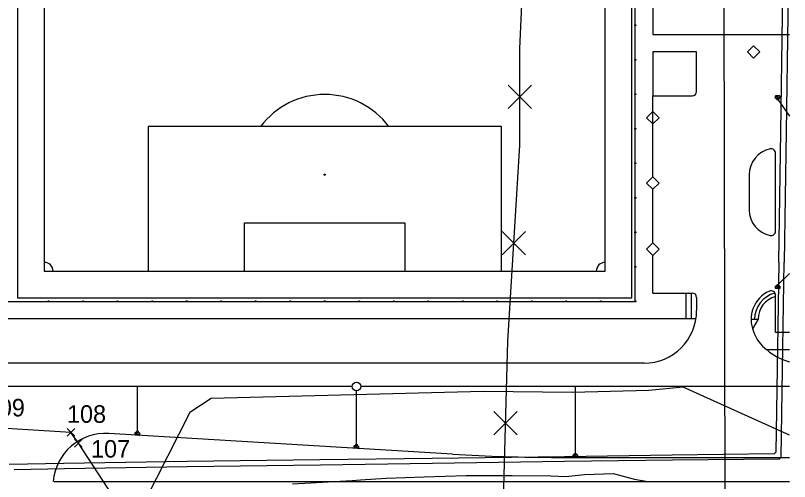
# Model space of a CAD drawing. Extents: x -264205 to -263744, y -1242450 to -1242050.
# Drawn here: x -264042.8 to -263954.5, y -1242315 to -1242261.8 of the extents above; entities that cross this region are included whole.
import ezdxf

# ---------------------------------------------------------------- set-up
doc = ezdxf.new("R2010")
doc.units = 0
for name, color, linetype in [('KFA_63-1_TELEKOM_PRELOZKA', 7, 'Continuous'), ('KFA_BODY_CISLO', 7, 'Continuous'), ('KFA_BODY_SYMBOL', 7, 'Continuous'), ('KFA_JESTV_IS_DSP', 7, 'Continuous'), ('KFA_SITUACIA_DSP', 7, 'Continuous'), ('KFA_TELEKOM_POVODNA_TRASA', 7, 'Continuous')]:
    doc.layers.add(name, color=color, linetype=linetype)

msp = doc.modelspace()

# ---------------------------------------------------------------- linework, layer by layer
at = {"layer": 'KFA_63-1_TELEKOM_PRELOZKA'}
msp.add_lwpolyline([(-264031.686, -1242316.628), (-264035.635, -1242310.616), (-264036.482, -1242309.377), (-264044.429, -1242308.908), (-264047.409, -1242310.561), (-264075.028, -1242310.403), (-264111.922, -1242310.326), (-264112.992, -1242310.115), (-264112.939, -1242300.049), (-264113.599, -1242298.941), (-264117.865, -1242295.81), (-264119.153, -1242294.416)], dxfattribs=at)
at = {"layer": 'KFA_BODY_SYMBOL'}
for p, q in [((-264036.924, -1242309.819), (-264036.04, -1242308.935)), ((-264036.04, -1242309.819), (-264036.924, -1242308.935)), ((-264036.482, -1242309.377), (-264036.482, -1242309.377)), ((-264036.077, -1242311.058), (-264035.193, -1242310.174)), ((-264035.193, -1242311.058), (-264036.077, -1242310.174)), ((-264035.635, -1242310.616), (-264035.635, -1242310.616))]:
    msp.add_line(p, q, dxfattribs=at)
at = {"layer": 'KFA_JESTV_IS_DSP'}
for p, q in [((-263955.264, -1242261.849), (-263954.978, -1242247.991)), ((-263954.47, -1242251.609), (-263954.644, -1242261.82)), ((-263961.971, -1242257.001), (-263961.846, -1242321.299)), ((-263955.442, -1242275.089), (-263955.264, -1242261.849)), ((-263954.644, -1242261.82), (-263954.858, -1242275.059)), ((-263955.703, -1242289.949), (-263955.442, -1242275.089)), ((-263954.858, -1242275.059), (-263955.079, -1242289.952)), ((-263955.703, -1242289.949), (-263955.826, -1242299.741)), ((-263955.217, -1242299.695), (-263955.079, -1242289.952)), ((-263955.826, -1242299.741), (-263956.021, -1242311.627)), ((-263955.441, -1242312.2), (-263955.217, -1242299.695)), ((-263966.621, -1242304.217), (-263970.539, -1242304.596)), ((-263954.47, -1242309.698), (-263966.621, -1242304.217)), ((-263989.391, -1242304.732), (-264020.458, -1242305.503)), ((-263979.267, -1242304.82), (-263989.391, -1242304.732)), ((-263970.539, -1242304.596), (-263979.267, -1242304.82)), ((-264020.458, -1242305.503), (-264022.907, -1242307.109)), ((-264022.907, -1242307.109), (-264028.018, -1242317.149)), ((-263980.158, -1242312.16), (-263995.27, -1242312.366)), ((-263967.857, -1242311.986), (-263980.158, -1242312.16)), ((-263956.215, -1242311.842), (-263967.857, -1242311.986)), ((-263956.021, -1242311.627), (-263956.215, -1242311.842)), ((-263955.668, -1242312.416), (-263955.441, -1242312.2)), ((-264037.278, -1242312.916), (-264043.542, -1242313.055)), ((-264023.233, -1242312.702), (-264037.278, -1242312.916)), ((-264008.055, -1242312.517), (-264023.233, -1242312.702)), ((-264023.206, -1242313.281), (-264007.988, -1242313.066)), ((-263995.27, -1242312.366), (-264008.055, -1242312.517)), ((-264007.988, -1242313.066), (-263995.203, -1242312.901)), ((-263995.203, -1242312.901), (-263980.143, -1242312.68)), ((-263980.143, -1242312.68), (-263967.842, -1242312.514)), ((-263967.842, -1242312.514), (-263955.668, -1242312.416)), ((-264042.951, -1242313.609), (-264037.232, -1242313.508)), ((-264037.232, -1242313.508), (-264023.206, -1242313.281)), ((-263977.86, -1242314.19), (-263974.61, -1242314.09)), ((-263974.61, -1242314.09), (-263972.17, -1242314.7)), ((-264011.19, -1242315.25), (-264004.4, -1242314.87)), ((-264004.4, -1242314.87), (-264003.44, -1242314.8)), ((-264003.44, -1242314.8), (-264000.5, -1242314.59)), ((-264000.5, -1242314.59), (-263996.15, -1242314.45)), ((-263996.15, -1242314.45), (-263991.36, -1242314.31)), ((-263991.36, -1242314.31), (-263986.12, -1242314.3)), ((-263986.12, -1242314.3), (-263981.72, -1242314.33)), ((-263981.72, -1242314.33), (-263979.98, -1242314.43)), ((-263979.98, -1242314.43), (-263977.86, -1242314.19)), ((-263972.17, -1242314.7), (-263970.63, -1242314.99))]:
    msp.add_line(p, q, dxfattribs=at)
at = {"layer": 'KFA_SITUACIA_DSP'}
for p, q in [((-264039.518, -1242190.982), (-264039.518, -1242290.982)), ((-263975.518, -1242290.982), (-263975.518, -1242190.982)), ((-263972.068, -1242294.432), (-263972.068, -1242255.057)), ((-263972.128, -1242262.932), (-263972.008, -1242262.932)), ((-263972.068, -1242262.992), (-263972.068, -1242262.872)), ((-263965.068, -1242265.982), (-263970.068, -1242265.982)), ((-263965.068, -1242270.482), (-263965.068, -1242265.982)), ((-263972.128, -1242266.87), (-263972.008, -1242266.87)), ((-263972.068, -1242266.93), (-263972.068, -1242266.81)), ((-263972.068, -1242270.867), (-263972.068, -1242270.747)), ((-263972.128, -1242270.807), (-263972.008, -1242270.807)), ((-263970.065, -1242280.238), (-263970.068, -1242270.982)), ((-263956.068, -1242270.982), (-263955.568, -1242270.982)), ((-263956.068, -1242271.272), (-263956.068, -1242270.982)), ((-263956.068, -1242270.982), (-263955.568, -1242271.272)), ((-263956.068, -1242270.982), (-263955.568, -1242271.272)), ((-263955.568, -1242270.982), (-263956.068, -1242270.982)), ((-263955.568, -1242271.272), (-263956.068, -1242271.272)), ((-263955.761, -1242271.455), (-263954.47, -1242273.324)), ((-263955.568, -1242270.982), (-263955.568, -1242271.272)), ((-263955.568, -1242271.272), (-263955.568, -1242270.982)), ((-263987.358, -1242274.482), (-264027.678, -1242274.482)), ((-264027.678, -1242274.482), (-264027.678, -1242290.982)), ((-263987.358, -1242290.982), (-263987.358, -1242274.482)), ((-263972.128, -1242274.745), (-263972.008, -1242274.745)), ((-263972.068, -1242274.805), (-263972.068, -1242274.685)), ((-263956.068, -1242286.432), (-263956.068, -1242277.533)), ((-263972.128, -1242278.682), (-263972.008, -1242278.682)), ((-263972.068, -1242278.742), (-263972.068, -1242278.622)), ((-263959.068, -1242279.982), (-263959.068, -1242283.982)), ((-263970.068, -1242287.775), (-263970.068, -1242281.649)), ((-263972.128, -1242282.62), (-263972.008, -1242282.62)), ((-263972.068, -1242282.68), (-263972.068, -1242282.56)), ((-264016.678, -1242290.982), (-264016.678, -1242285.482)), ((-264016.678, -1242285.482), (-263998.358, -1242285.482)), ((-263998.358, -1242285.482), (-263998.358, -1242290.982)), ((-263972.128, -1242286.557), (-263972.008, -1242286.557)), ((-263972.068, -1242286.617), (-263972.068, -1242286.497)), ((-263970.068, -1242293.482), (-263970.068, -1242289.189)), ((-264039.518, -1242290.982), (-263975.518, -1242290.982)), ((-263972.128, -1242290.495), (-263972.008, -1242290.495)), ((-263972.068, -1242290.555), (-263972.068, -1242290.435)), ((-263955.747, -1242292.522), (-263954.47, -1242291.259)), ((-263956.068, -1242292.692), (-263955.568, -1242292.692)), ((-263956.068, -1242292.982), (-263956.068, -1242292.692)), ((-263956.068, -1242292.692), (-263955.568, -1242292.982)), ((-263956.068, -1242292.692), (-263955.568, -1242292.982)), ((-263955.568, -1242292.692), (-263956.068, -1242292.692)), ((-263955.568, -1242292.692), (-263955.568, -1242292.982)), ((-263955.568, -1242292.982), (-263955.568, -1242292.692)), ((-263970.068, -1242293.482), (-263965.568, -1242293.482)), ((-263966.314, -1242293.482), (-263966.314, -1242296.432)), ((-263965.684, -1242293.482), (-263965.684, -1242296.432)), ((-263955.568, -1242292.982), (-263956.068, -1242292.982)), ((-263956.068, -1242297.982), (-263956.068, -1242293.737)), ((-264045.118, -1242294.432), (-263972.068, -1242294.432)), ((-264038.969, -1242294.432), (-264039.089, -1242294.432)), ((-264039.029, -1242294.492), (-264039.029, -1242294.372)), ((-264035.03, -1242294.432), (-264035.15, -1242294.432)), ((-264035.09, -1242294.492), (-264035.09, -1242294.372)), ((-264031.091, -1242294.432), (-264031.211, -1242294.432)), ((-264031.151, -1242294.492), (-264031.151, -1242294.372)), ((-264027.152, -1242294.432), (-264027.272, -1242294.432)), ((-264027.212, -1242294.492), (-264027.212, -1242294.372)), ((-264023.213, -1242294.432), (-264023.333, -1242294.432)), ((-264023.273, -1242294.492), (-264023.273, -1242294.372)), ((-264019.274, -1242294.432), (-264019.394, -1242294.432)), ((-264019.334, -1242294.492), (-264019.334, -1242294.372)), ((-264015.336, -1242294.432), (-264015.456, -1242294.432)), ((-264015.396, -1242294.492), (-264015.396, -1242294.372)), ((-264011.397, -1242294.432), (-264011.517, -1242294.432)), ((-264011.457, -1242294.492), (-264011.457, -1242294.372)), ((-264007.458, -1242294.432), (-264007.578, -1242294.432)), ((-264007.518, -1242294.492), (-264007.518, -1242294.372)), ((-264003.519, -1242294.432), (-264003.639, -1242294.432)), ((-264003.579, -1242294.492), (-264003.579, -1242294.372)), ((-263999.58, -1242294.432), (-263999.7, -1242294.432)), ((-263999.64, -1242294.492), (-263999.64, -1242294.372)), ((-263995.641, -1242294.432), (-263995.761, -1242294.432)), ((-263995.701, -1242294.492), (-263995.701, -1242294.372)), ((-263991.702, -1242294.432), (-263991.822, -1242294.432)), ((-263991.762, -1242294.492), (-263991.762, -1242294.372)), ((-263987.763, -1242294.432), (-263987.883, -1242294.432)), ((-263987.823, -1242294.492), (-263987.823, -1242294.372)), ((-263983.824, -1242294.432), (-263983.944, -1242294.432)), ((-263983.884, -1242294.492), (-263983.884, -1242294.372)), ((-263979.886, -1242294.432), (-263980.006, -1242294.432)), ((-263979.946, -1242294.492), (-263979.946, -1242294.372)), ((-263975.947, -1242294.432), (-263976.067, -1242294.432)), ((-263976.007, -1242294.492), (-263976.007, -1242294.372)), ((-263972.128, -1242294.432), (-263972.008, -1242294.432)), ((-263972.068, -1242294.492), (-263972.068, -1242294.372)), ((-263965.068, -1242293.982), (-263965.068, -1242295.482)), ((-263954.47, -1242297.982), (-263956.068, -1242297.982)), ((-263954.47, -1242299.982), (-263957.036, -1242299.982)), ((-263971.068, -1242301.482), (-264112.961, -1242301.482)), ((-264004.396, -1242304.147), (-264044.527, -1242304.147)), ((-264028.895, -1242309.22), (-264028.89, -1242304.147)), ((-263954.47, -1242304.147), (-264003.396, -1242304.147)), ((-263978.913, -1242311.742), (-263978.913, -1242304.147)), ((-264003.896, -1242310.723), (-264003.896, -1242304.647)), ((-263992.94, -1242311.872), (-264032.171, -1242309.514)), ((-264032.171, -1242309.514), (-264032.171, -1242309.514)), ((-264029.162, -1242309.695), (-264029.144, -1242309.405)), ((-264029.144, -1242309.405), (-264028.645, -1242309.435)), ((-264029.144, -1242309.405), (-264028.663, -1242309.725)), ((-264029.144, -1242309.405), (-264028.663, -1242309.725)), ((-264028.645, -1242309.435), (-264029.144, -1242309.405)), ((-264028.645, -1242309.435), (-264028.663, -1242309.725)), ((-264028.663, -1242309.725), (-264028.645, -1242309.435)), ((-264028.663, -1242309.725), (-264029.162, -1242309.695)), ((-264004.163, -1242311.197), (-264004.146, -1242310.908)), ((-264003.664, -1242311.227), (-264004.163, -1242311.197)), ((-264004.146, -1242310.908), (-264003.646, -1242310.938)), ((-264004.146, -1242310.908), (-264003.664, -1242311.227)), ((-264004.146, -1242310.908), (-264003.664, -1242311.227)), ((-264003.646, -1242310.938), (-264004.146, -1242310.908)), ((-264003.646, -1242310.938), (-264003.664, -1242311.227)), ((-264003.664, -1242311.227), (-264003.646, -1242310.938)), ((-263980.94, -1242312.232), (-263954.47, -1242312.232)), ((-263979.163, -1242311.942), (-263978.663, -1242311.942)), ((-263979.163, -1242312.232), (-263979.163, -1242311.942)), ((-263979.163, -1242311.942), (-263978.663, -1242312.232)), ((-263979.163, -1242311.942), (-263978.663, -1242312.232)), ((-263978.663, -1242311.942), (-263979.163, -1242311.942)), ((-263978.663, -1242312.232), (-263979.163, -1242312.232)), ((-263978.663, -1242311.942), (-263978.663, -1242312.232)), ((-263978.663, -1242312.232), (-263978.663, -1242311.942)), ((-264038.443, -1242314.982), (-263954.47, -1242314.982))]:
    msp.add_line(p, q, dxfattribs=at)
for points in [[(-264042.568, -1242294.032), (-263972.468, -1242294.032), (-263972.468, -1242187.932), (-264042.568, -1242187.932)], [(-263958.568, -1242265.275), (-263957.861, -1242265.982), (-263958.568, -1242266.689), (-263959.275, -1242265.982)], [(-263970.068, -1242272.775), (-263969.361, -1242273.482), (-263970.068, -1242274.189), (-263970.775, -1242273.482)], [(-263970.068, -1242280.235), (-263969.361, -1242280.942), (-263970.068, -1242281.649), (-263970.775, -1242280.942)], [(-263970.068, -1242287.775), (-263969.361, -1242288.482), (-263970.068, -1242289.189), (-263970.775, -1242288.482)]]:
    msp.add_lwpolyline(points, close=True, dxfattribs=at)
for points in [[(-263954.47, -1242254.982), (-263970.077, -1242254.982), (-263970.077, -1242263.982), (-263954.47, -1242263.982)], [(-263970.068, -1242265.982), (-263970.068, -1242270.982), (-263965.568, -1242270.982)], [(-263965.143, -1242296.432), (-264120.018, -1242296.432), (-264120.282, -1242296.432)], [(-263958.859, -1242296.482), (-263958.059, -1242296.482), (-263958.688, -1242297.562)]]:
    msp.add_lwpolyline(points, dxfattribs=at)
for centre, radius in [((-263972.068, -1242262.932), 0.06), ((-263972.068, -1242266.87), 0.06), ((-263972.068, -1242270.807), 0.06), ((-263955.818, -1242271.373), 0.1), ((-263972.068, -1242274.745), 0.06), ((-263972.068, -1242278.682), 0.06), ((-264007.518, -1242279.982), 0.06), ((-263972.068, -1242282.62), 0.06), ((-263972.068, -1242286.557), 0.06), ((-263972.068, -1242290.495), 0.06), ((-263955.818, -1242292.592), 0.1), ((-264039.029, -1242294.432), 0.06), ((-264035.09, -1242294.432), 0.06), ((-264031.151, -1242294.432), 0.06), ((-264027.212, -1242294.432), 0.06), ((-264023.273, -1242294.432), 0.06), ((-264019.334, -1242294.432), 0.06), ((-264015.396, -1242294.432), 0.06), ((-264011.457, -1242294.432), 0.06), ((-264007.518, -1242294.432), 0.06), ((-264003.579, -1242294.432), 0.06), ((-263999.64, -1242294.432), 0.06), ((-263995.701, -1242294.432), 0.06), ((-263991.762, -1242294.432), 0.06), ((-263987.823, -1242294.432), 0.06), ((-263983.884, -1242294.432), 0.06), ((-263979.946, -1242294.432), 0.06), ((-263976.007, -1242294.432), 0.06), ((-263972.068, -1242294.432), 0.06), ((-264003.896, -1242304.147), 0.5), ((-264028.895, -1242309.32), 0.1), ((-264003.896, -1242310.823), 0.1), ((-263978.913, -1242311.842), 0.1)]:
    msp.add_circle(centre, radius, dxfattribs=at)
for centre, radius, start, end in [((-263965.568, -1242270.482), 0.5, 270, 0), ((-264007.518, -1242279.982), 9.15, 36.94821, 143.05179), ((-263956.068, -1242279.982), 3, 101.53696, 180), ((-263956.568, -1242277.533), 0.5, 0, 101.53696), ((-264007.518, -1242279.982), 0.0303, 90, 270), ((-264007.518, -1242279.982), 0.0303, 270, 90), ((-263956.068, -1242283.982), 3, 180, 258.46304), ((-263956.568, -1242286.432), 0.5, 258.46304, 0), ((-264039.518, -1242290.982), 1, 0, 90), ((-263975.518, -1242290.982), 1, 90, 180), ((-263965.568, -1242293.982), 0.5, 0, 90), ((-263955.359, -1242296.482), 3.5, 113.75985, 203.57818), ((-263955.359, -1242296.482), 3.1, 104.54571, 180), ((-263956.568, -1242293.737), 0.5, 0, 113.75985), ((-263955.359, -1242296.482), 2.7, 105.21758, 180), ((-263971.068, -1242295.482), 6, 270, 0), ((-263954.444, -1242296.485), 4.353, 198.7173, 233.45125), ((-263953.068, -1242295.482), 6, 228.59038, 256.48819), ((-264032.531, -1242315.503), 6, 86.56019, 175.02052), ((-263980.94, -1242112.232), 200, 266.56019, 270)]:
    msp.add_arc(centre, radius, start, end, dxfattribs=at)
at = {"layer": 'KFA_TELEKOM_POVODNA_TRASA'}
for p, q in [((-263985.267, -1242265.602), (-263984.635, -1242252.165)), ((-263985.239, -1242276.615), (-263985.267, -1242265.602)), ((-263986.579, -1242272.434), (-263983.927, -1242269.782)), ((-263983.927, -1242272.434), (-263986.579, -1242269.782)), ((-263986.634, -1242298.981), (-263985.239, -1242276.615)), ((-263987.262, -1242289.124), (-263984.61, -1242286.472)), ((-263984.61, -1242289.124), (-263987.262, -1242286.472)), ((-263987.11, -1242317.682), (-263986.634, -1242298.981)), ((-263988.198, -1242309.657), (-263985.546, -1242307.005)), ((-263985.546, -1242309.657), (-263988.198, -1242307.005))]:
    msp.add_line(p, q, dxfattribs=at)

# ---------------------------------------------------------------- texts
at = {"layer": 'KFA_BODY_CISLO'}
for s, p in [('109', (-264046.197, -1242307.56)), ('108', (-264036.932, -1242308.286)), ('107', (-264034.188, -1242312.259))]:
    msp.add_text(s, height=2, dxfattribs=at).set_placement(p)

doc.saveas('drawing.dxf')
